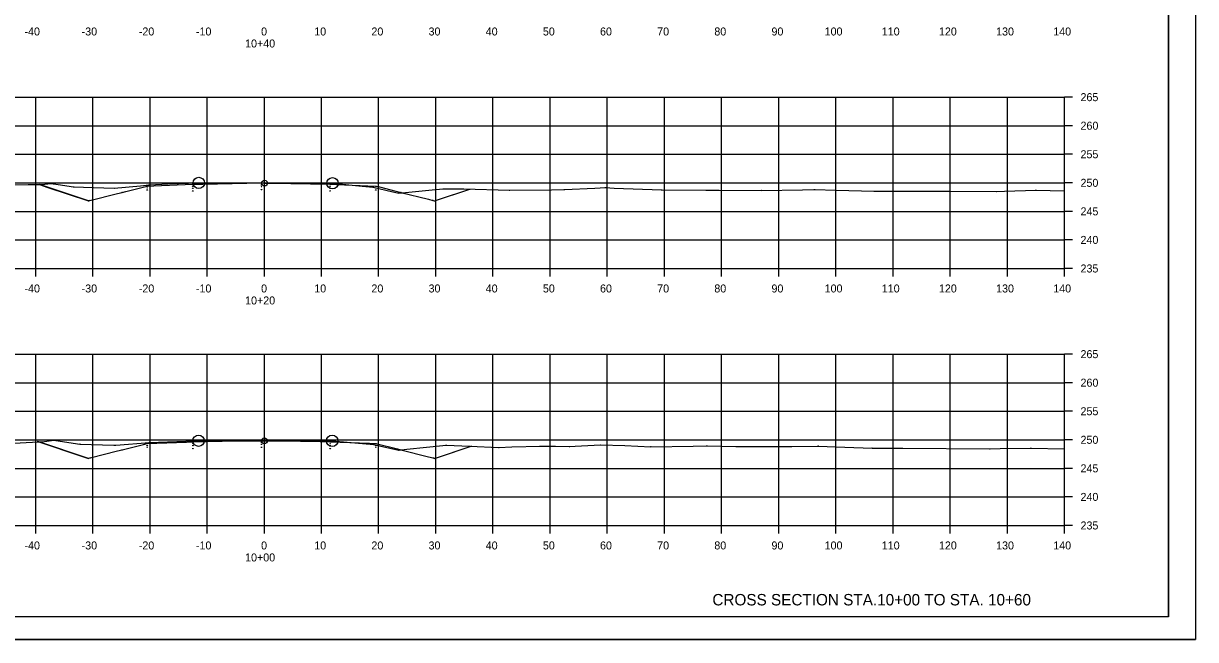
# Model space of a CAD drawing. Extents: x 1300404 to 1323571, y 234004 to 252077.
# Drawn here: x 1315675.1 to 1315880.2, y 243408.5 to 243516.4 of the extents above; entities that cross this region are included whole.
import ezdxf

# ---------------------------------------------------------------- set-up
doc = ezdxf.new("R2010")
doc.units = 0
for name, color, linetype in [('Default', 7, 'Continuous'), ('R_Axis', 7, 'Continuous'), ('R_Axis Annot', 7, 'Continuous'), ('R_Draft', 7, 'Continuous'), ('R_Exist Surface', 7, 'Continuous'), ('R_Fin Surface', 7, 'Continuous'), ('R_Grid', 7, 'Continuous'), ('R_No Plot', 7, 'Continuous')]:
    doc.layers.add(name, color=color, linetype=linetype)

msp = doc.modelspace()

# ---------------------------------------------------------------- linework, layer by layer
at = {"layer": 'Default'}
for q in [(1315875.46, 243617.93), (1315559.28, 243412.47)]:
    msp.add_line((1315875.46, 243412.47), q, dxfattribs=at)
at = {"layer": 'R_Axis'}
for p, q in [((1315857.28, 243473.47), (1315857.28, 243503.47)), ((1315858.68, 243503.47), (1315857.28, 243503.47)), ((1315858.68, 243498.47), (1315857.28, 243498.47)), ((1315858.68, 243493.47), (1315857.28, 243493.47)), ((1315858.68, 243488.47), (1315857.28, 243488.47)), ((1315858.68, 243483.47), (1315857.28, 243483.47)), ((1315858.68, 243478.47), (1315857.28, 243478.47)), ((1315577.28, 243473.47), (1315857.28, 243473.47)), ((1315677.28, 243472.07), (1315677.28, 243473.47)), ((1315687.28, 243472.07), (1315687.28, 243473.47)), ((1315697.28, 243472.07), (1315697.28, 243473.47)), ((1315707.28, 243472.07), (1315707.28, 243473.47)), ((1315717.28, 243472.07), (1315717.28, 243473.47)), ((1315727.28, 243472.07), (1315727.28, 243473.47)), ((1315737.28, 243472.07), (1315737.28, 243473.47)), ((1315747.28, 243472.07), (1315747.28, 243473.47)), ((1315757.28, 243472.07), (1315757.28, 243473.47)), ((1315767.28, 243472.07), (1315767.28, 243473.47)), ((1315777.28, 243472.07), (1315777.28, 243473.47)), ((1315787.28, 243472.07), (1315787.28, 243473.47)), ((1315797.28, 243472.07), (1315797.28, 243473.47)), ((1315807.28, 243472.07), (1315807.28, 243473.47)), ((1315817.28, 243472.07), (1315817.28, 243473.47)), ((1315827.28, 243472.07), (1315827.28, 243473.47)), ((1315837.28, 243472.07), (1315837.28, 243473.47)), ((1315847.28, 243472.07), (1315847.28, 243473.47)), ((1315857.28, 243472.07), (1315857.28, 243473.47)), ((1315858.68, 243473.47), (1315857.28, 243473.47)), ((1315857.28, 243428.47), (1315857.28, 243458.47)), ((1315858.68, 243458.47), (1315857.28, 243458.47)), ((1315858.68, 243453.47), (1315857.28, 243453.47)), ((1315858.68, 243448.47), (1315857.28, 243448.47)), ((1315858.68, 243443.47), (1315857.28, 243443.47)), ((1315858.68, 243438.47), (1315857.28, 243438.47)), ((1315858.68, 243433.47), (1315857.28, 243433.47)), ((1315577.28, 243428.47), (1315857.28, 243428.47)), ((1315677.28, 243427.07), (1315677.28, 243428.47)), ((1315687.28, 243427.07), (1315687.28, 243428.47)), ((1315697.28, 243427.07), (1315697.28, 243428.47)), ((1315707.28, 243427.07), (1315707.28, 243428.47)), ((1315717.28, 243427.07), (1315717.28, 243428.47)), ((1315727.28, 243427.07), (1315727.28, 243428.47)), ((1315737.28, 243427.07), (1315737.28, 243428.47)), ((1315747.28, 243427.07), (1315747.28, 243428.47)), ((1315757.28, 243427.07), (1315757.28, 243428.47)), ((1315767.28, 243427.07), (1315767.28, 243428.47)), ((1315777.28, 243427.07), (1315777.28, 243428.47)), ((1315787.28, 243427.07), (1315787.28, 243428.47)), ((1315797.28, 243427.07), (1315797.28, 243428.47)), ((1315807.28, 243427.07), (1315807.28, 243428.47)), ((1315817.28, 243427.07), (1315817.28, 243428.47)), ((1315827.28, 243427.07), (1315827.28, 243428.47)), ((1315837.28, 243427.07), (1315837.28, 243428.47)), ((1315847.28, 243427.07), (1315847.28, 243428.47)), ((1315857.28, 243427.07), (1315857.28, 243428.47)), ((1315858.68, 243428.47), (1315857.28, 243428.47))]:
    msp.add_line(p, q, dxfattribs=at)
at = {"layer": 'R_Draft'}
for points in [[(1315677.94, 243488.2), (1315677.99, 243488.1), (1315677.89, 243488.1)], [(1315677.94, 243488.2), (1315677.99, 243488.1), (1315677.89, 243488.1)], [(1315679.92, 243488.41), (1315679.97, 243488.31), (1315679.87, 243488.31)], [(1315696.77, 243487.95), (1315696.82, 243487.85), (1315696.72, 243487.85)], [(1315697.15, 243488.18), (1315697.2, 243488.08), (1315697.1, 243488.08)], [(1315704.77, 243488.27), (1315704.82, 243488.17), (1315704.72, 243488.17)], [(1315704.77, 243487.93), (1315704.82, 243487.83), (1315704.72, 243487.83)], [(1315716.77, 243488.51), (1315716.82, 243488.41), (1315716.72, 243488.41)], [(1315716.77, 243488.17), (1315716.82, 243488.07), (1315716.72, 243488.07)], [(1315728.77, 243488.27), (1315728.82, 243488.17), (1315728.72, 243488.17)], [(1315728.77, 243487.93), (1315728.82, 243487.83), (1315728.72, 243487.83)], [(1315736.77, 243487.95), (1315736.82, 243487.85), (1315736.72, 243487.85)], [(1315683.89, 243487.82), (1315683.94, 243487.72), (1315683.84, 243487.72)], [(1315691.03, 243487.58), (1315691.08, 243487.48), (1315690.98, 243487.48)], [(1315692.4, 243486.85), (1315692.45, 243486.75), (1315692.35, 243486.75)], [(1315696.77, 243487.62), (1315696.82, 243487.52), (1315696.72, 243487.52)], [(1315696.77, 243487.29), (1315696.82, 243487.19), (1315696.72, 243487.19)], [(1315704.77, 243487.6), (1315704.82, 243487.5), (1315704.72, 243487.5)], [(1315704.77, 243487.1), (1315704.82, 243487), (1315704.72, 243487)], [(1315716.77, 243487.84), (1315716.82, 243487.74), (1315716.72, 243487.74)], [(1315716.77, 243487.34), (1315716.82, 243487.24), (1315716.72, 243487.24)], [(1315728.77, 243487.6), (1315728.82, 243487.5), (1315728.72, 243487.5)], [(1315728.77, 243487.1), (1315728.82, 243487), (1315728.72, 243487)], [(1315736.33, 243487.77), (1315736.38, 243487.67), (1315736.28, 243487.67)], [(1315736.77, 243487.61), (1315736.82, 243487.51), (1315736.72, 243487.51)], [(1315736.77, 243487.28), (1315736.82, 243487.18), (1315736.72, 243487.18)], [(1315740.81, 243486.73), (1315740.86, 243486.63), (1315740.76, 243486.63)], [(1315741.15, 243486.85), (1315741.2, 243486.75), (1315741.1, 243486.75)], [(1315748.63, 243487.47), (1315748.68, 243487.37), (1315748.58, 243487.37)], [(1315753.25, 243487.42), (1315753.3, 243487.32), (1315753.2, 243487.32)], [(1315753.25, 243487.42), (1315753.3, 243487.32), (1315753.2, 243487.32)], [(1315760.18, 243487.25), (1315760.23, 243487.15), (1315760.13, 243487.15)], [(1315769.82, 243487.34), (1315769.87, 243487.24), (1315769.77, 243487.24)], [(1315776.94, 243487.68), (1315776.99, 243487.58), (1315776.89, 243487.58)], [(1315786.76, 243487.29), (1315786.81, 243487.19), (1315786.71, 243487.19)], [(1315795.8, 243487.25), (1315795.85, 243487.15), (1315795.75, 243487.15)], [(1315804.24, 243487.2), (1315804.29, 243487.1), (1315804.19, 243487.1)], [(1315813.51, 243487.33), (1315813.56, 243487.23), (1315813.46, 243487.23)], [(1315823.95, 243487.07), (1315824, 243486.97), (1315823.9, 243486.97)], [(1315845.35, 243487.01), (1315845.4, 243486.91), (1315845.3, 243486.91)], [(1315852.25, 243487.24), (1315852.3, 243487.14), (1315852.2, 243487.14)], [(1315686.49, 243485.35), (1315686.54, 243485.25), (1315686.44, 243485.25)], [(1315686.77, 243485.45), (1315686.82, 243485.35), (1315686.72, 243485.35)], [(1315746.77, 243485.45), (1315746.82, 243485.35), (1315746.72, 243485.35)], [(1315747.06, 243485.35), (1315747.11, 243485.25), (1315747.01, 243485.25)], [(1315677.66, 243443.22), (1315677.71, 243443.12), (1315677.61, 243443.12)], [(1315677.66, 243443.22), (1315677.71, 243443.12), (1315677.61, 243443.12)], [(1315680.44, 243443.48), (1315680.49, 243443.38), (1315680.39, 243443.38)], [(1315685.02, 243442.78), (1315685.07, 243442.68), (1315684.97, 243442.68)], [(1315696.79, 243442.86), (1315696.84, 243442.76), (1315696.74, 243442.76)], [(1315697.19, 243443.07), (1315697.24, 243442.97), (1315697.14, 243442.97)], [(1315704.79, 243443.18), (1315704.84, 243443.08), (1315704.74, 243443.08)], [(1315704.79, 243442.85), (1315704.84, 243442.75), (1315704.74, 243442.75)], [(1315716.79, 243443.42), (1315716.84, 243443.32), (1315716.74, 243443.32)], [(1315716.79, 243443.09), (1315716.84, 243442.99), (1315716.74, 243442.99)], [(1315728.79, 243443.18), (1315728.84, 243443.08), (1315728.74, 243443.08)], [(1315728.79, 243442.85), (1315728.84, 243442.75), (1315728.74, 243442.75)], [(1315736.79, 243442.86), (1315736.84, 243442.76), (1315736.74, 243442.76)], [(1315691.15, 243442.57), (1315691.2, 243442.47), (1315691.1, 243442.47)], [(1315692.41, 243441.77), (1315692.46, 243441.67), (1315692.36, 243441.67)], [(1315696.79, 243442.53), (1315696.84, 243442.43), (1315696.74, 243442.43)], [(1315696.79, 243442.2), (1315696.84, 243442.1), (1315696.74, 243442.1)], [(1315704.79, 243442.51), (1315704.84, 243442.41), (1315704.74, 243442.41)], [(1315704.79, 243442.01), (1315704.84, 243441.91), (1315704.74, 243441.91)], [(1315716.79, 243442.76), (1315716.84, 243442.66), (1315716.74, 243442.66)], [(1315716.79, 243442.25), (1315716.84, 243442.15), (1315716.74, 243442.15)], [(1315728.79, 243442.52), (1315728.84, 243442.42), (1315728.74, 243442.42)], [(1315728.79, 243442.01), (1315728.84, 243441.91), (1315728.74, 243441.91)], [(1315736.41, 243442.68), (1315736.46, 243442.58), (1315736.36, 243442.58)], [(1315736.79, 243442.53), (1315736.84, 243442.43), (1315736.74, 243442.43)], [(1315736.79, 243442.2), (1315736.84, 243442.1), (1315736.74, 243442.1)], [(1315740.79, 243441.7), (1315740.84, 243441.6), (1315740.74, 243441.6)], [(1315741.17, 243441.77), (1315741.22, 243441.67), (1315741.12, 243441.67)], [(1315749.07, 243442.59), (1315749.12, 243442.49), (1315749.02, 243442.49)], [(1315753.45, 243442.39), (1315753.5, 243442.29), (1315753.4, 243442.29)], [(1315753.45, 243442.39), (1315753.5, 243442.29), (1315753.4, 243442.29)], [(1315758.29, 243442.17), (1315758.34, 243442.07), (1315758.24, 243442.07)], [(1315765.52, 243442.42), (1315765.57, 243442.32), (1315765.47, 243442.32)], [(1315770.65, 243442.34), (1315770.7, 243442.24), (1315770.6, 243442.24)], [(1315776.07, 243442.61), (1315776.12, 243442.51), (1315776.02, 243442.51)], [(1315784.89, 243442.31), (1315784.94, 243442.21), (1315784.84, 243442.21)], [(1315794.71, 243442.48), (1315794.76, 243442.38), (1315794.66, 243442.38)], [(1315803.26, 243442.32), (1315803.31, 243442.22), (1315803.21, 243442.22)], [(1315814.18, 243442.43), (1315814.23, 243442.33), (1315814.13, 243442.33)], [(1315823.6, 243442.08), (1315823.65, 243441.98), (1315823.55, 243441.98)], [(1315844.23, 243441.91), (1315844.28, 243441.81), (1315844.18, 243441.81)], [(1315851.36, 243442.07), (1315851.41, 243441.97), (1315851.31, 243441.97)], [(1315686.51, 243440.27), (1315686.56, 243440.17), (1315686.46, 243440.17)], [(1315686.79, 243440.36), (1315686.84, 243440.26), (1315686.74, 243440.26)], [(1315746.79, 243440.36), (1315746.84, 243440.26), (1315746.74, 243440.26)], [(1315747.07, 243440.27), (1315747.12, 243440.17), (1315747.02, 243440.17)]]:
    msp.add_lwpolyline(points, close=True, dxfattribs=at)
at = {"layer": 'R_Exist Surface'}
for points in [[(1315673.04, 243488.09), (1315675.97, 243488.2), (1315678.33, 243488.18), (1315679.92, 243488.36), (1315681.19, 243488.19), (1315683.89, 243487.77), (1315687.41, 243487.66), (1315691.03, 243487.53), (1315695.58, 243487.92), (1315697.15, 243488.13), (1315700.47, 243488.28), (1315705.8, 243488.45), (1315710.42, 243488.44), (1315717.32, 243488.43), (1315724.43, 243488.41), (1315729.2, 243488.39), (1315734.41, 243487.9), (1315736.33, 243487.72), (1315739.78, 243486.91), (1315740.81, 243486.68), (1315747.2, 243487.29), (1315748.63, 243487.42), (1315752.19, 243487.42), (1315760.18, 243487.2), (1315767.5, 243487.25), (1315769.82, 243487.29), (1315775.08, 243487.56), (1315776.94, 243487.63), (1315778.49, 243487.55), (1315786.76, 243487.24), (1315794.54, 243487.2), (1315795.8, 243487.2), (1315796.86, 243487.2), (1315804.24, 243487.15), (1315811.43, 243487.24), (1315813.51, 243487.28), (1315817.3, 243487.17), (1315823.95, 243487.02), (1315837.21, 243486.98), (1315845.35, 243486.96), (1315846.79, 243487.01), (1315852.25, 243487.19), (1315857.28, 243487.06)], [(1315673.52, 243442.89), (1315678.8, 243443.18), (1315680.44, 243443.43), (1315683.06, 243443), (1315685.02, 243442.73), (1315690.96, 243442.52), (1315691.15, 243442.52), (1315691.27, 243442.53), (1315697.19, 243443.02), (1315705.09, 243443.28), (1315705.77, 243443.31), (1315716.68, 243443.3), (1315717.29, 243443.3), (1315717.91, 243443.3), (1315729.15, 243443.29), (1315729.76, 243443.24), (1315736.41, 243442.63), (1315736.93, 243442.52), (1315740.79, 243441.65), (1315742.2, 243441.81), (1315749.07, 243442.54), (1315753.23, 243442.35), (1315758.29, 243442.12), (1315760.56, 243442.25), (1315765.52, 243442.37), (1315768.24, 243442.33), (1315770.65, 243442.29), (1315771.69, 243442.33), (1315776.07, 243442.56), (1315780.33, 243442.48), (1315784.89, 243442.26), (1315792.3, 243442.34), (1315794.71, 243442.43), (1315799.78, 243442.32), (1315803.26, 243442.27), (1315809.55, 243442.3), (1315814.18, 243442.38), (1315818.85, 243442.19), (1315823.6, 243442.03), (1315828.98, 243442), (1315844.23, 243441.86), (1315846.01, 243441.93), (1315851.36, 243442.02), (1315857.28, 243441.9)]]:
    msp.add_lwpolyline(points, dxfattribs=at)
at = {"layer": 'R_Fin Surface'}
for points in [[(1315677.94, 243488.15), (1315679.21, 243487.73), (1315686.49, 243485.3), (1315686.53, 243485.32), (1315686.77, 243485.4), (1315691.57, 243486.6), (1315692.4, 243486.8), (1315693.04, 243486.96), (1315696.77, 243487.9), (1315697.94, 243487.95), (1315704.77, 243488.22), (1315706.51, 243488.25), (1315716.77, 243488.46), (1315718.5, 243488.42), (1315728.77, 243488.22), (1315729.92, 243488.17), (1315736.77, 243487.9), (1315737.4, 243487.74), (1315741.15, 243486.8), (1315745.98, 243485.6), (1315746.77, 243485.4), (1315746.81, 243485.38), (1315747.06, 243485.3), (1315747.93, 243485.59), (1315753.25, 243487.37)], [(1315677.66, 243443.17), (1315685.27, 243440.63), (1315686.51, 243440.22), (1315686.55, 243440.23), (1315686.79, 243440.31), (1315691.59, 243441.51), (1315692.41, 243441.72), (1315696.15, 243442.65), (1315696.79, 243442.81), (1315703.63, 243443.08), (1315704.79, 243443.13), (1315715.06, 243443.34), (1315716.79, 243443.37), (1315727.07, 243443.16), (1315728.79, 243443.13), (1315735.65, 243442.86), (1315736.79, 243442.81), (1315740.55, 243441.87), (1315741.17, 243441.72), (1315745.99, 243440.51), (1315746.79, 243440.31), (1315746.83, 243440.3), (1315747.07, 243440.22), (1315747.95, 243440.51), (1315753.45, 243442.34)]]:
    msp.add_lwpolyline(points, dxfattribs=at)
at = {"layer": 'R_Grid'}
for p, q in [((1315577.28, 243503.47), (1315857.28, 243503.47)), ((1315677.28, 243473.47), (1315677.28, 243503.47)), ((1315687.28, 243473.47), (1315687.28, 243503.47)), ((1315697.28, 243473.47), (1315697.28, 243503.47)), ((1315707.28, 243473.47), (1315707.28, 243503.47)), ((1315717.28, 243473.47), (1315717.28, 243503.47)), ((1315727.28, 243473.47), (1315727.28, 243503.47)), ((1315737.28, 243473.47), (1315737.28, 243503.47)), ((1315747.28, 243473.47), (1315747.28, 243503.47)), ((1315757.28, 243473.47), (1315757.28, 243503.47)), ((1315767.28, 243473.47), (1315767.28, 243503.47)), ((1315777.28, 243473.47), (1315777.28, 243503.47)), ((1315787.28, 243473.47), (1315787.28, 243503.47)), ((1315797.28, 243473.47), (1315797.28, 243503.47)), ((1315807.28, 243473.47), (1315807.28, 243503.47)), ((1315817.28, 243473.47), (1315817.28, 243503.47)), ((1315827.28, 243473.47), (1315827.28, 243503.47)), ((1315837.28, 243473.47), (1315837.28, 243503.47)), ((1315847.28, 243473.47), (1315847.28, 243503.47)), ((1315857.28, 243473.47), (1315857.28, 243503.47)), ((1315577.28, 243498.47), (1315857.28, 243498.47)), ((1315577.28, 243493.47), (1315857.28, 243493.47)), ((1315577.28, 243488.47), (1315857.28, 243488.47)), ((1315577.28, 243483.47), (1315857.28, 243483.47)), ((1315577.28, 243478.47), (1315857.28, 243478.47)), ((1315577.28, 243473.47), (1315857.28, 243473.47)), ((1315577.28, 243458.47), (1315857.28, 243458.47)), ((1315677.28, 243428.47), (1315677.28, 243458.47)), ((1315687.28, 243428.47), (1315687.28, 243458.47)), ((1315697.28, 243428.47), (1315697.28, 243458.47)), ((1315707.28, 243428.47), (1315707.28, 243458.47)), ((1315717.28, 243428.47), (1315717.28, 243458.47)), ((1315727.28, 243428.47), (1315727.28, 243458.47)), ((1315737.28, 243428.47), (1315737.28, 243458.47)), ((1315747.28, 243428.47), (1315747.28, 243458.47)), ((1315757.28, 243428.47), (1315757.28, 243458.47)), ((1315767.28, 243428.47), (1315767.28, 243458.47)), ((1315777.28, 243428.47), (1315777.28, 243458.47)), ((1315787.28, 243428.47), (1315787.28, 243458.47)), ((1315797.28, 243428.47), (1315797.28, 243458.47)), ((1315807.28, 243428.47), (1315807.28, 243458.47)), ((1315817.28, 243428.47), (1315817.28, 243458.47)), ((1315827.28, 243428.47), (1315827.28, 243458.47)), ((1315837.28, 243428.47), (1315837.28, 243458.47)), ((1315847.28, 243428.47), (1315847.28, 243458.47)), ((1315857.28, 243428.47), (1315857.28, 243458.47)), ((1315577.28, 243453.47), (1315857.28, 243453.47)), ((1315577.28, 243448.47), (1315857.28, 243448.47)), ((1315577.28, 243443.47), (1315857.28, 243443.47)), ((1315577.28, 243438.47), (1315857.28, 243438.47)), ((1315577.28, 243433.47), (1315857.28, 243433.47)), ((1315577.28, 243428.47), (1315857.28, 243428.47))]:
    msp.add_line(p, q, dxfattribs=at)
at = {"layer": 'R_No Plot'}
msp.add_line((1315546.87, 243408.49), (1315880.21, 243408.49), dxfattribs=at)
for points in [[(1315546.87, 243621.83), (1315880.21, 243621.83), (1315880.21, 243408.49), (1315546.87, 243408.49)], [(1315793.2, 243617.93), (1315793.2, 243608.05), (1315828.93, 243608.05), (1315828.93, 243605.13), (1315852.13, 243605.13), (1315852.13, 243583.01), (1315875.46, 243583.01), (1315875.46, 243412.47), (1315559.28, 243412.47), (1315559.28, 243617.93)]]:
    msp.add_lwpolyline(points, close=True, dxfattribs=at)
for points in [[(1315686.49, 243485.3), (1315677.94, 243488.15)], [(1315686.77, 243485.4), (1315686.49, 243485.3), (1315677.94, 243488.15)], [(1315686.77, 243485.4), (1315686.49, 243485.3), (1315677.94, 243488.15)], [(1315686.77, 243485.4), (1315686.49, 243485.3), (1315677.94, 243488.15)], [(1315686.77, 243485.4), (1315686.49, 243485.3), (1315677.94, 243488.15)], [(1315686.77, 243485.4), (1315686.49, 243485.3), (1315677.94, 243488.15)], [(1315746.77, 243485.4), (1315747.06, 243485.3), (1315753.25, 243487.37)], [(1315746.77, 243485.4), (1315747.06, 243485.3), (1315753.25, 243487.37)], [(1315746.77, 243485.4), (1315747.06, 243485.3), (1315753.25, 243487.37)], [(1315746.77, 243485.4), (1315747.06, 243485.3), (1315753.25, 243487.37)], [(1315686.51, 243440.22), (1315677.66, 243443.17)], [(1315686.79, 243440.31), (1315686.51, 243440.22), (1315677.66, 243443.17)], [(1315686.79, 243440.31), (1315686.51, 243440.22), (1315677.66, 243443.17)], [(1315686.79, 243440.31), (1315686.51, 243440.22), (1315677.66, 243443.17)], [(1315686.79, 243440.31), (1315686.51, 243440.22), (1315677.66, 243443.17)], [(1315686.79, 243440.31), (1315686.51, 243440.22), (1315677.66, 243443.17)], [(1315746.79, 243440.31), (1315747.07, 243440.22), (1315753.45, 243442.34)], [(1315746.79, 243440.31), (1315747.07, 243440.22), (1315753.45, 243442.34)], [(1315746.79, 243440.31), (1315747.07, 243440.22), (1315753.45, 243442.34)], [(1315746.79, 243440.31), (1315747.07, 243440.22), (1315753.45, 243442.34)]]:
    msp.add_lwpolyline(points, dxfattribs=at)
for centre, radius in [((1315705.8, 243488.45), 1), ((1315717.32, 243488.43), 0.5), ((1315729.2, 243488.39), 1), ((1315705.77, 243443.31), 1), ((1315717.29, 243443.3), 0.5), ((1315729.15, 243443.29), 1)]:
    msp.add_circle(centre, radius, dxfattribs=at)

# ---------------------------------------------------------------- texts
at = {"layer": 'R_Axis Annot'}
for s, p in [('-40', (1315675.31, 243514.27)), ('-30', (1315685.31, 243514.27)), ('-20', (1315695.31, 243514.27)), ('-10', (1315705.31, 243514.27)), ('0', (1315716.71, 243514.27)), ('10', (1315726.01, 243514.27)), ('20', (1315736.01, 243514.27)), ('30', (1315746.01, 243514.27)), ('40', (1315756.01, 243514.27)), ('50', (1315766.01, 243514.27)), ('60', (1315776.01, 243514.27)), ('70', (1315786.01, 243514.27)), ('80', (1315796.01, 243514.27)), ('90', (1315806.01, 243514.27)), ('100', (1315815.31, 243514.27)), ('110', (1315825.31, 243514.27)), ('120', (1315835.31, 243514.27)), ('130', (1315845.31, 243514.27)), ('140', (1315855.31, 243514.27)), ('10+40', (1315713.91, 243512.17)), ('265', (1315860.08, 243502.77)), ('260', (1315860.08, 243497.77)), ('255', (1315860.08, 243492.77)), ('250', (1315860.08, 243487.77)), ('245', (1315860.08, 243482.77)), ('240', (1315860.08, 243477.77)), ('235', (1315860.08, 243472.77)), ('-40', (1315675.31, 243469.27)), ('-30', (1315685.31, 243469.27)), ('-20', (1315695.31, 243469.27)), ('-10', (1315705.31, 243469.27)), ('0', (1315716.71, 243469.27)), ('10', (1315726.01, 243469.27)), ('20', (1315736.01, 243469.27)), ('30', (1315746.01, 243469.27)), ('40', (1315756.01, 243469.27)), ('50', (1315766.01, 243469.27)), ('60', (1315776.01, 243469.27)), ('70', (1315786.01, 243469.27)), ('80', (1315796.01, 243469.27)), ('90', (1315806.01, 243469.27)), ('100', (1315815.31, 243469.27)), ('110', (1315825.31, 243469.27)), ('120', (1315835.31, 243469.27)), ('130', (1315845.31, 243469.27)), ('140', (1315855.31, 243469.27)), ('10+20', (1315713.91, 243467.17)), ('265', (1315860.08, 243457.77)), ('260', (1315860.08, 243452.77)), ('255', (1315860.08, 243447.77)), ('250', (1315860.08, 243442.77)), ('245', (1315860.08, 243437.77)), ('240', (1315860.08, 243432.77)), ('235', (1315860.08, 243427.77)), ('-40', (1315675.31, 243424.27)), ('-30', (1315685.31, 243424.27)), ('-20', (1315695.31, 243424.27)), ('-10', (1315705.31, 243424.27)), ('0', (1315716.71, 243424.27)), ('10', (1315726.01, 243424.27)), ('20', (1315736.01, 243424.27)), ('30', (1315746.01, 243424.27)), ('40', (1315756.01, 243424.27)), ('50', (1315766.01, 243424.27)), ('60', (1315776.01, 243424.27)), ('70', (1315786.01, 243424.27)), ('80', (1315796.01, 243424.27)), ('90', (1315806.01, 243424.27)), ('100', (1315815.31, 243424.27)), ('110', (1315825.31, 243424.27)), ('120', (1315835.31, 243424.27)), ('130', (1315845.31, 243424.27)), ('140', (1315855.31, 243424.27)), ('10+00', (1315713.91, 243422.17))]:
    msp.add_text(s, height=1.4, dxfattribs=at).set_placement(p)
at = {"layer": 'R_Draft'}
msp.add_text('CROSS SECTION STA.10+00 TO STA. 10+60', height=2, dxfattribs=at).set_placement((1315795.67, 243414.47))

doc.saveas('drawing.dxf')
